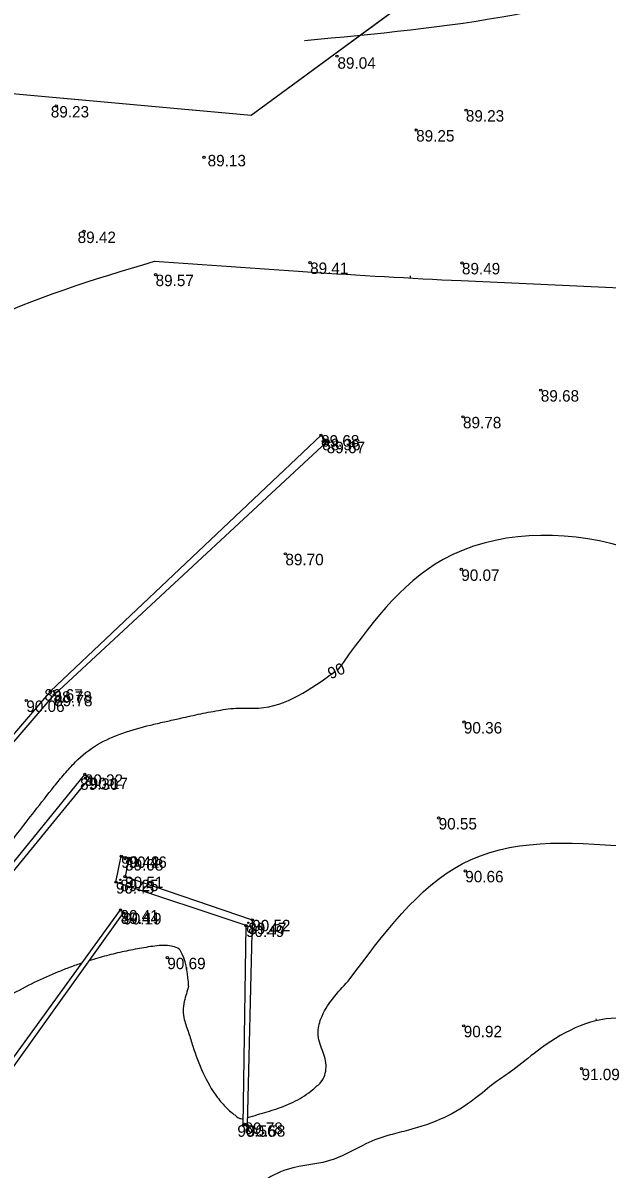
# Model space of a CAD drawing. Extents: x 316000 to 728450, y 314368 to 726000.
# Drawn here: x 726846 to 727037.5, y 316067.8 to 316443.6 of the extents above; entities that cross this region are included whole.
import ezdxf

# ---------------------------------------------------------------- set-up
doc = ezdxf.new("R2010")
doc.units = 0
for name, color, linetype in [('20', 7, 'Continuous'), ('HIDG_ELEM_####_####_#', 7, 'Continuous'), ('HIDG_GRAV_####_####_#', 7, 'Continuous'), ('RAMI_UZMR_####_####_#', 7, 'Continuous'), ('RELJ_AATZ_####_TKST_#', 7, 'Continuous'), ('RELJ_ELEM_####_####_#', 7, 'Continuous'), ('RELJ_HORZ_####_TKST_#', 7, 'Continuous'), ('RELJ_HORZ_PAMT_####_#', 7, 'Continuous'), ('RELJ_HORZ_RESN_####_#', 7, 'Continuous')]:
    doc.layers.add(name, color=color, linetype=linetype)

msp = doc.modelspace()

# ---------------------------------------------------------------- linework, layer by layer
at = {"layer": '20'}
for p, q in [((726920.82, 316413.39), (727228.71, 316639.18)), ((726741.03, 316429.64), (726920.82, 316413.39))]:
    msp.add_line(p, q, dxfattribs=at)
at = {"layer": 'HIDG_ELEM_####_####_#'}
for centre in [(726944.3, 316306.48), (726856.06, 316224.48), (726866.52, 316196.14), (726879.51, 316169.46), (726877.91, 316162.69), (726919.89, 316148.59), (726918.68, 316082.52)]:
    msp.add_circle(centre, 0.225, dxfattribs=at)
at = {"layer": 'HIDG_GRAV_####_####_#'}
for points in [[(726856.29, 316223.31), (726945.62, 316306.28), (726943.76, 316308.45), (726855.02, 316224.51)], [(726855.02, 316224.51), (726741.72, 316092.54), (726743.18, 316091.45), (726856.29, 316223.31)], [(726736.1, 316036.98), (726866.31, 316197.24)], [(726866.31, 316197.24), (726867.89, 316196.14), (726737.09, 316036.39)], [(726878.23, 316170.37), (726880.69, 316169.69), (726879.5, 316163.71), (726921.18, 316149.55), (726919.48, 316082.21), (726918.26, 316082.23), (726919.17, 316147.68), (726876.51, 316161.9), (726878.23, 316170.37)], [(726878.01, 316152.77), (726878.91, 316151.79), (726805.97, 316050.03), (726804.2, 316051.06), (726878.01, 316152.77)]]:
    msp.add_lwpolyline(points, dxfattribs=at)
at = {"layer": 'RAMI_UZMR_####_####_#'}
msp.add_lwpolyline([(725662, 315676.73), (726089.69, 315915.19), (726207.18, 316075.15), (726354.66, 316148.59), (726468.38, 316318.09), (726620.03, 316392.72), (726621.75, 316399.51), (726696.34, 316417.27), (726741.03, 316429.64), (726920.82, 316413.39), (727228.71, 316639.18)], dxfattribs=at)
at = {"layer": 'RELJ_ELEM_####_####_#'}
for centre in [(726948.97, 316432.7), (726856.95, 316416.37), (726991.24, 316415), (726974.94, 316408.46), (726905.42, 316399.56), (726866.07, 316375.3), (726940.17, 316365.04), (726989.95, 316364.91), (726889.51, 316361.05), (727015.8, 316323.2), (726990.3, 316314.45), (726943.76, 316308.45), (726945.62, 316306.28), (726932.07, 316269.54), (726989.73, 316264.42), (726855.02, 316224.51), (726847.12, 316221.45), (726856.29, 316223.31), (726990.58, 316214.38), (726866.31, 316197.24), (726867.89, 316196.14), (726982.31, 316182.92), (726878.23, 316170.37), (726880.69, 316169.69), (726991.04, 316165.59), (726876.51, 316161.9), (726879.5, 316163.71), (726878.01, 316152.77), (726878.91, 316151.79), (726921.18, 316149.55), (726919.17, 316147.68), (726893.36, 316137.11), (726990.54, 316114.8), (727029.15, 316100.74), (726918.26, 316082.23), (726918.68, 316082.52), (726919.48, 316082.21)]:
    msp.add_circle(centre, 0.375, dxfattribs=at)
at = {"layer": 'RELJ_HORZ_PAMT_####_#'}
for p, q in [((726972.97, 316360.67), (726972.94, 316360.17)), ((727033.82, 316117.14), (727033.94, 316116.65))]:
    msp.add_line(p, q, dxfattribs=at)
for points in [[(727456.51, 316240.15), (727418.33, 316353.94), (727339.57, 316385.92), (727241.81, 316464.36), (727148.74, 316501.5), (727073.69, 316467.38), (726938.33, 316437.74)], [(726791.13, 316282.13), (726796.88, 316309.71), (726889.11, 316365.46)], [(726889.11, 316365.46), (726989.71, 316359.11), (727065.34, 316355.24), (727118.66, 316353.23), (727193.1, 316356.75), (727271.08, 316305.77), (727322.62, 316289.32), (727445.44, 316221.13), (727462.4, 316205.59)], [(726952.69, 316129.49), (726990.07, 316167.92), (727104.45, 316172.11), (727203.94, 316207.14), (727248.52, 316197.85), (727345.06, 316166.14), (727393.91, 316115.17), (727412.13, 316078.87), (727401.59, 316010.94), (727415.61, 315973.59), (727441.47, 315904.64)], [(726900.35, 316127.84), (726898.26, 316138.31), (726897.2, 316139.9), (726895.2, 316140.8), (726892.85, 316141.16), (726890.72, 316141.1), (726884.98, 316140.27), (726879.22, 316139.17), (726873.45, 316137.79), (726867.69, 316136.13)], [(726865.4, 316135.38), (726861.46, 316133.99), (726857.53, 316132.46), (726849.72, 316128.96), (726834.35, 316120.15), (726819.49, 316108.79), (726812.31, 316102.12), (726808.79, 316098.52), (726807.05, 316096.65), (726805.33, 316094.74), (726803.43, 316092.29), (726801.99, 316089.77), (726800.25, 316084.54), (726799.73, 316073.62), (726800.13, 316062.62), (726799.54, 316057.29), (726798.38, 316053.42), (726797.81, 316052.17), (726794.41, 316045.26), (726790.63, 316038.7), (726785.92, 316032.85), (726783.03, 316030.32), (726781.42, 316029.18), (726780.58, 316028.63), (726779.7, 316028.12), (726777.19, 316027), (726774.65, 316026.42), (726769.53, 316026.63), (726759.18, 316030.57), (726748.83, 316035.56), (726743.72, 316037.08), (726741.19, 316037.36), (726738.69, 316037.22), (726738.07, 316037.01), (726737.45, 316036.68), (726736.82, 316036.41), (726736.18, 316036.37), (726731.47, 316037.35)], [(726900.35, 316127.84), (726899.59, 316125.33), (726898.89, 316122.78), (726898.51, 316119.72), (726898.92, 316116.87), (726900.32, 316112.53), (726901.72, 316108.13), (726905.02, 316099.45), (726909.72, 316091.41), (726912.87, 316087.81), (726914.7, 316086.15), (726915.68, 316085.36), (726916.71, 316084.59), (726918.29, 316084.33)], [(726919.54, 316084.68), (726919.7, 316084.73), (726926.11, 316086.61), (726932.36, 316088.79), (726938.29, 316091.86), (726941.08, 316093.9), (726942.42, 316095.08), (726943.73, 316096.37), (726945.4, 316101.2), (726944.2, 316106.75), (726942.77, 316112.3), (726943.73, 316117.11), (726952.69, 316129.49)], [(727407.26, 315826.81), (727420.88, 315859.78), (727421.31, 315861.98), (727420.84, 315873.16), (727415.63, 315882.87), (727395.8, 315899.43), (727371.45, 315914.61), (727360.58, 315922.6), (727355.76, 315932.78), (727350.87, 315945.8), (727343.65, 315965.03), (727334.62, 315981.5), (727324.71, 316005.53), (727317, 316014.24), (727310.95, 316025.93), (727306.22, 316036.97), (727300.2, 316049.01), (727293.8, 316067.18), (727252.55, 316104.18), (727204.11, 316093.45), (727172.31, 316071.99), (727104.82, 316081.23), (727087.15, 316092.31), (727070.62, 316103.93), (727040.63, 316117.26), (727014.6, 316106.53), (727006.58, 316100.22), (727000.85, 316096.21), (726994.11, 316090.82), (726983.98, 316084.66), (726972.39, 316080.59), (726966.37, 316079.01), (726958.49, 316076.14), (726948.07, 316071.06), (726932.7, 316067.7), (726916.22, 316058.14), (726880.98, 316039.68), (726836.99, 316020.53), (726807.52, 316005.55), (726787.17, 315993.15), (726764.31, 315989.32), (726742.06, 315986.79), (726725.03, 315990.27), (726708.15, 315999.77), (726691.28, 316009.5), (726674.31, 316013.66), (726659.02, 316010.43), (726643.66, 316003.77), (726628.26, 315996.72), (726612.85, 315992.34), (726600.2, 315993.32), (726587.04, 315996.97), (726574, 315999.47), (726567.72, 315999.1), (726561.71, 315997.03), (726548.35, 315992.52), (726536.61, 315988.25), (726525.25, 315984.49), (726513.03, 315977.96), (726485.95, 315966.35), (726456.08, 315949.13), (726439.28, 315937.58), (726388.53, 315922.53), (726290.27, 315916.68), (726240.08, 315917.6), (726226.6, 315921.61), (726211.69, 315923.04), (726191.22, 315924.62), (726136.88, 315919.22), (726111.29, 315920.51), (726086.94, 315922.23)]]:
    msp.add_spline(points, degree=3, dxfattribs=at)
at = {"layer": 'RELJ_HORZ_RESN_####_#'}
for points in [[(727340.76, 316250.08), (727332.04, 316255.64), (727318.71, 316262.42), (727304.95, 316267.5), (727297.91, 316269.42), (727290.75, 316270.92), (727276.09, 316271.87), (727261.35, 316270), (727239.41, 316270.19), (727213.24, 316268.7), (727191.55, 316268), (727178.74, 316269.54), (727168.45, 316270.04), (727154.43, 316268.32), (727141.78, 316266.61), (727117.11, 316267.47), (727107.76, 316269.33), (727098.41, 316269.34), (727085.57, 316267.51), (727072.6, 316264.87), (727042.51, 316271.93), (726983.82, 316267.7), (726949.15, 316231.4)], [(726789.32, 316110.02), (726816.72, 316141.94), (726820.48, 316146.96), (726823.74, 316151.48), (726825.07, 316153.41), (726826.35, 316155.38), (726827.65, 316157.34), (726829, 316159.25), (726831.34, 316162.2), (726833.8, 316165.05), (726836.27, 316167.88), (726838.68, 316170.78), (726844.26, 316177.93), (726849.82, 316185.1), (726856.28, 316193.33), (726859.64, 316197.36), (726861.41, 316199.35), (726863.24, 316201.32), (726870.46, 316206.98), (726878.81, 316210.78), (726887.81, 316213.39), (726892.39, 316214.46), (726896.94, 316215.46), (726903.51, 316216.92), (726910.08, 316218.19), (726916.66, 316218.97), (726923.26, 316218.98), (726948.27, 316230.9)]]:
    msp.add_spline(points, degree=3, dxfattribs=at)

# ---------------------------------------------------------------- texts
at = {"layer": 'RELJ_AATZ_####_TKST_#'}
for s, p in [('89.04', (726949.13, 316428.58)), ('89.23', (726855.15, 316412.6)), ('89.23', (726991.24, 316411.25)), ('89.25', (726974.94, 316404.71)), ('89.13', (726906.58, 316396.59)), ('89.42', (726863.95, 316371.43)), ('89.41', (726940.17, 316361.29)), ('89.49', (726989.95, 316361.16)), ('89.57', (726889.51, 316357.3)), ('89.68', (727015.8, 316319.45)), ('89.78', (726990.3, 316310.7)), ('89.68', (726943.76, 316304.7)), ('88.36', (726944.16, 316303.49)), ('89.67', (726945.62, 316302.53)), ('89.70', (726932.07, 316265.79)), ('90.07', (726989.73, 316260.67)), ('89.67', (726853.05, 316221.42)), ('88.78', (726856.06, 316220.73)), ('90.06', (726847.12, 316217.7)), ('89.78', (726856.29, 316219.56)), ('90.36', (726990.58, 316210.63)), ('89.30', (726864.76, 316192.17)), ('90.32', (726866.31, 316193.49)), ('90.17', (726867.89, 316192.39)), ('90.55', (726982.31, 316179.17)), ('90.42', (726878.23, 316166.62)), ('89.08', (726879.51, 316165.71)), ('90.46', (726880.64, 316166.57)), ('90.66', (726991.04, 316161.84)), ('90.45', (726876.51, 316158.15)), ('89.25', (726877.91, 316158.94)), ('90.51', (726879.5, 316159.96)), ('90.41', (726878.01, 316149.02)), ('89.44', (726878.08, 316148.21)), ('90.19', (726878.91, 316148.04)), ('90.52', (726921.18, 316145.8)), ('90.49', (726919.17, 316143.93)), ('89.47', (726919.89, 316144.84)), ('90.69', (726893.36, 316133.36)), ('90.92', (726990.54, 316111.05)), ('91.09', (727029.15, 316096.99)), ('90.56', (726916.32, 316078.42)), ('89.78', (726918.66, 316079.36)), ('90.58', (726919.48, 316078.46))]:
    msp.add_text(s, height=3.75, dxfattribs=at).set_placement(p)
at = {"layer": 'RELJ_HORZ_####_TKST_#'}
msp.add_text('90', height=3.75, rotation=23.2757, dxfattribs=at).set_placement((726946.91, 316228.37))

doc.saveas('drawing.dxf')
